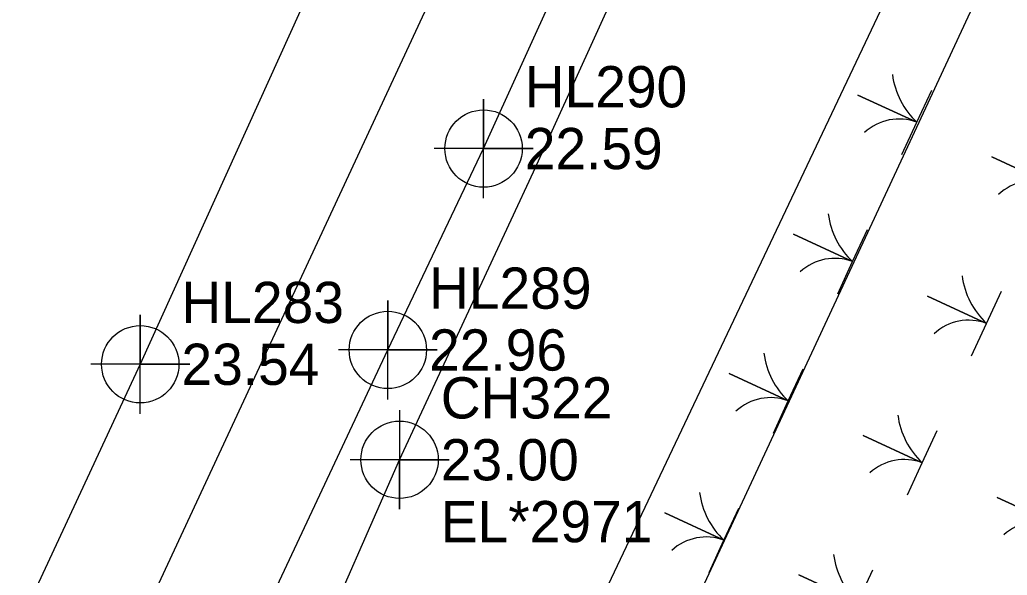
# Model space of a CAD drawing. Extents: x 2532037 to 2533565, y 713396 to 716867.
# Drawn here: x 2532881.8 to 2532941.6, y 715681.4 to 715715.1 of the extents above; entities that cross this region are included whole.
import ezdxf

# ---------------------------------------------------------------- set-up
doc = ezdxf.new("R2010")
doc.units = 0
for name, color, linetype in [('Exist Environmental Wetland Boundary', 7, 'Continuous'), ('Exist Horizontal Alignment', 7, 'Continuous'), ('Exist Right of Way Line', 7, 'Continuous'), ('Exist Roads Soil', 7, 'Continuous'), ('Exist Roads Soil Cogo Elevation', 7, 'Continuous'), ('Exist Roads Soil Cogo Number', 7, 'Continuous'), ('Exist Roads Soil Cogo Point CELL', 7, 'Continuous'), ('Exist Utilities Telephone UG Cable SUE LOS B Cogo Comment', 7, 'Continuous'), ('Exist Utilities Telephone UG Cable SUE LOS B Cogo Elevation', 7, 'Continuous'), ('Exist Utilities Telephone UG Cable SUE LOS B Cogo Number', 7, 'Continuous'), ('Exist Utilities Telephone UG Cable SUE LOS B Cogo Point CELL', 7, 'Continuous'), ('Exist Utilities Telephone UG Cable SUE LOS C', 7, 'Continuous'), ('Scratch_Level_1', 7, 'Continuous')]:
    doc.layers.add(name, color=color, linetype=linetype)

msp = doc.modelspace()

# ---------------------------------------------------------------- linework, layer by layer
at = {"layer": 'Exist Environmental Wetland Boundary'}
msp.add_line((2532911.894, 715669.143), (2532945.52, 715740.024), dxfattribs=at)
at = {"layer": 'Exist Horizontal Alignment'}
msp.add_line((2532720.816, 715316.862), (2532922.836, 715751.084), dxfattribs=at)
at = {"layer": 'Exist Right of Way Line'}
msp.add_line((2532748.017, 715304.207), (2532950.036, 715738.429), dxfattribs=at)
at = {"layer": 'Exist Roads Soil'}
for points in [[(2533033.002, 715963.552), (2533014.441, 715935.484), (2532992.666, 715901.095), (2532976.471, 715871.314), (2532962.05, 715845.129), (2532943.271, 715807.995), (2532921.982, 715764.363), (2532902.685, 715724.284), (2532889.068, 715694.204), (2532879.255, 715673.169), (2532870.648, 715655.411), (2532876.571, 715652.013), (2532882.435, 715649.375)], [(2532882.435, 715649.375), (2532884.446, 715653.582), (2532893.832, 715673.236), (2532904.082, 715695.07), (2532909.886, 715707.279), (2532923.655, 715737.545), (2532935.371, 715761.586), (2532947.639, 715787.122), (2532960.723, 715812.473), (2532979.299, 715846.297), (2532995.343, 715875.457), (2533008.573, 715897.69), (2533027.701, 715928.616), (2533038.596, 715945.654), (2533044.798, 715955.275)]]:
    msp.add_lwpolyline(points, dxfattribs=at)
at = {"layer": 'Exist Roads Soil Cogo Point CELL'}
for points in [[(2532909.886, 715704.279), (2532909.886, 715710.279), (2532909.886, 715707.279), (2532912.886, 715707.279), (2532906.886, 715707.279)], [(2532904.082, 715692.07), (2532904.082, 715698.07), (2532904.082, 715695.07), (2532907.082, 715695.07), (2532901.082, 715695.07)], [(2532889.068, 715691.204), (2532889.068, 715697.204), (2532889.068, 715694.204), (2532892.068, 715694.204), (2532886.068, 715694.204)]]:
    msp.add_lwpolyline(points, dxfattribs=at)
for centre in [(2532909.886, 715707.279), (2532904.082, 715695.07), (2532889.068, 715694.204)]:
    msp.add_circle(centre, 2.344, dxfattribs=at)
at = {"layer": 'Exist Utilities Telephone UG Cable SUE LOS B Cogo Point CELL'}
msp.add_lwpolyline([(2532904.794, 715691.417), (2532904.794, 715685.417), (2532904.794, 715688.417), (2532907.794, 715688.417), (2532901.794, 715688.417)], dxfattribs=at)
msp.add_circle((2532904.794, 715688.417), 2.344, dxfattribs=at)
at = {"layer": 'Exist Utilities Telephone UG Cable SUE LOS C'}
msp.add_lwpolyline([(2532903.546, 715664.845), (2532899.751, 715668.696), (2532897.819, 715670.962), (2532899.436, 715676.209), (2532904.794, 715688.417), (2532912.91, 715705.872), (2532926.672, 715736.124), (2532938.373, 715760.133), (2532950.625, 715785.635), (2532963.667, 715810.905), (2532982.222, 715844.69), (2532998.238, 715873.8), (2533011.425, 715895.96), (2533023.694, 715915.797)], dxfattribs=at)
at = {"layer": 'Scratch_Level_1'}
for points in [[(2532935.26, 715706.919), (2532936.162, 715708.872), (2532932.58, 715710.525), (2532936.162, 715708.872), (2532937.063, 715710.824)], [(2532943.382, 715703.17), (2532944.283, 715705.122), (2532940.701, 715706.776), (2532944.283, 715705.122), (2532945.185, 715707.075)], [(2532931.362, 715698.475), (2532932.263, 715700.427), (2532928.682, 715702.081), (2532932.263, 715700.427), (2532933.165, 715702.38)], [(2532939.483, 715694.725), (2532940.385, 715696.678), (2532936.803, 715698.331), (2532940.385, 715696.678), (2532941.286, 715698.63)], [(2532927.464, 715690.03), (2532928.365, 715691.983), (2532924.783, 715693.636), (2532928.365, 715691.983), (2532929.266, 715693.935)], [(2532935.585, 715686.281), (2532936.486, 715688.233), (2532932.905, 715689.887), (2532936.486, 715688.233), (2532937.388, 715690.186)], [(2532943.706, 715682.532), (2532944.608, 715684.484), (2532941.026, 715686.138), (2532944.608, 715684.484), (2532945.509, 715686.436)], [(2532923.565, 715681.586), (2532924.466, 715683.538), (2532920.885, 715685.192), (2532924.466, 715683.538), (2532925.368, 715685.491)], [(2532931.687, 715677.837), (2532932.588, 715679.789), (2532929.006, 715681.443), (2532932.588, 715679.789), (2532933.489, 715681.741)]]:
    msp.add_lwpolyline(points, dxfattribs=at)
for centre, radius, start, end in [((2532939.449, 715712.377), 4.806, 187.34643, 226.84116), ((2532935.078, 715705.994), 3.075, 69.35932, 132.75394), ((2532943.199, 715702.245), 3.075, 69.35932, 132.75394), ((2532935.551, 715703.933), 4.806, 187.34643, 226.84116), ((2532931.18, 715697.55), 3.075, 69.35932, 132.75394), ((2532943.672, 715700.183), 4.806, 187.34643, 226.84116), ((2532939.301, 715693.801), 3.075, 69.35932, 132.75394), ((2532931.652, 715695.488), 4.806, 187.34643, 226.84116), ((2532927.281, 715689.106), 3.075, 69.35932, 132.75394), ((2532939.774, 715691.739), 4.806, 187.34643, 226.84116), ((2532935.403, 715685.356), 3.075, 69.35932, 132.75394), ((2532927.754, 715687.044), 4.806, 187.34643, 226.84116), ((2532943.524, 715681.607), 3.075, 69.35932, 132.75394), ((2532923.383, 715680.661), 3.075, 69.35932, 132.75394), ((2532935.875, 715683.295), 4.806, 187.34643, 226.84116)]:
    msp.add_arc(centre, radius, start, end, dxfattribs=at)

# ---------------------------------------------------------------- texts
at = {"layer": 'Exist Roads Soil Cogo Elevation'}
for s, p in [('22.59', (2532912.386, 715706.029)), ('22.96', (2532906.582, 715693.82)), ('23.54', (2532891.568, 715692.954))]:
    msp.add_text(s, height=2.5, dxfattribs=at).set_placement(p)
at = {"layer": 'Exist Roads Soil Cogo Number'}
for s, p in [('HL290', (2532912.386, 715709.779)), ('HL289', (2532906.582, 715697.57)), ('HL283', (2532891.568, 715696.704))]:
    msp.add_text(s, height=2.5, dxfattribs=at).set_placement(p)
at = {"layer": 'Exist Utilities Telephone UG Cable SUE LOS B Cogo Comment'}
msp.add_text('EL*2971', height=2.5, dxfattribs=at).set_placement((2532907.294, 715683.417))
at = {"layer": 'Exist Utilities Telephone UG Cable SUE LOS B Cogo Elevation'}
msp.add_text('23.00', height=2.5, dxfattribs=at).set_placement((2532907.294, 715687.167))
at = {"layer": 'Exist Utilities Telephone UG Cable SUE LOS B Cogo Number'}
msp.add_text('CH322', height=2.5, dxfattribs=at).set_placement((2532907.294, 715690.917))

doc.saveas('drawing.dxf')
